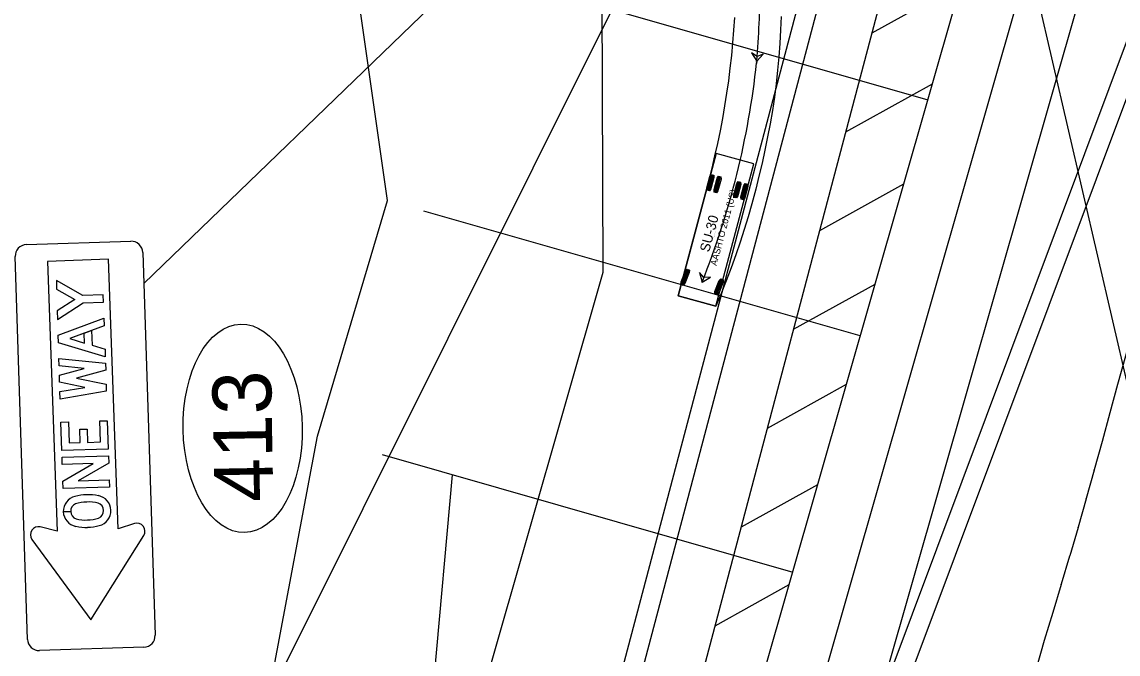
# Model space of a CAD drawing. Extents: x 2096670 to 2098561, y 684033 to 689893.
# Drawn here: x 2097725.3 to 2097948.6, y 689091.3 to 689219.9 of the extents above; entities that cross this region are included whole.
import ezdxf

# ---------------------------------------------------------------- set-up
doc = ezdxf.new("R2010")
doc.units = 0
for name, color, linetype in [('Exist CMT EOP', 7, 'Continuous'), ('Exist Sign E Stop CELL', 7, 'Continuous'), ('Old_Level_63', 7, 'Continuous'), ('Prop Guardrail', 7, 'Continuous'), ('Prop Retaining Wall', 7, 'Continuous'), ('Prop Sign E One Way_Right CELL', 7, 'Continuous'), ('Scratch_Level_2', 7, 'Continuous'), ('Scratch_Level_4', 7, 'Continuous')]:
    doc.layers.add(name, color=color, linetype=linetype)

msp = doc.modelspace()

# ---------------------------------------------------------------- linework, layer by layer
at = {"layer": 'Exist CMT EOP'}
for p, q in [((2097898.92, 689078.74), (2098112.47, 689824.77)), ((2097859.86, 688985.9), (2097968.29, 689364.69)), ((2097822.79, 688994.35), (2097898.87, 689281.72)), ((2097826.66, 688993.33), (2097898.28, 689263.84)), ((2097838.2, 688990.02), (2097909.63, 689259.86)), ((2097875.84, 689085.34), (2097924.62, 689255.73)), ((2097898.47, 689217.7), (2097916.61, 689227.76)), ((2097898.92, 689078.74), (2097951.73, 689219.64)), ((2097902.76, 689077.64), (2097955.58, 689218.54)), ((2097893.15, 689197.59), (2097910.77, 689207.37)), ((2097887.82, 689177.48), (2097904.94, 689186.97)), ((2097882.5, 689157.37), (2097899.1, 689166.58)), ((2097877.18, 689137.26), (2097893.26, 689146.19)), ((2097871.85, 689117.15), (2097887.42, 689125.79)), ((2097866.53, 689097.04), (2097881.58, 689105.4))]:
    msp.add_line(p, q, dxfattribs=at)
at = {"layer": 'Exist Sign E Stop CELL'}
msp.add_line((2097764.4, 689059.94), (2097879.48, 689290.46), dxfattribs=at)
at = {"layer": 'Old_Level_63'}
for p, q in [((2097866.69, 689193.14), (2097858.95, 689164.15)), ((2097874.42, 689191.08), (2097866.69, 689193.14)), ((2097866.68, 689162.09), (2097874.42, 689191.08)), ((2097864.91, 689185.68), (2097865.77, 689188.9)), ((2097865.11, 689185.63), (2097865.97, 689188.85)), ((2097865.32, 689185.57), (2097866.17, 689188.79)), ((2097866.36, 689185.29), (2097867.22, 689188.51)), ((2097866.56, 689185.24), (2097867.42, 689188.46)), ((2097866.76, 689185.18), (2097867.62, 689188.41)), ((2097870.39, 689184.22), (2097871.25, 689187.44)), ((2097870.59, 689184.16), (2097871.45, 689187.38)), ((2097870.79, 689184.11), (2097871.65, 689187.33)), ((2097871.84, 689183.83), (2097872.7, 689187.05)), ((2097872.04, 689183.78), (2097872.9, 689187)), ((2097872.24, 689183.72), (2097873.1, 689186.94)), ((2097859.59, 689166.49), (2097860.83, 689169.58)), ((2097859.78, 689166.41), (2097861.02, 689169.51)), ((2097859.97, 689166.34), (2097861.22, 689169.43)), ((2097866.49, 689164.55), (2097867.72, 689167.64)), ((2097866.68, 689164.47), (2097867.91, 689167.57)), ((2097866.87, 689164.39), (2097868.1, 689167.49)), ((2097858.95, 689164.15), (2097866.68, 689162.09)), ((2097866.68, 689162.09), (2097866.68, 689162.09))]:
    msp.add_line(p, q, dxfattribs=at)
for points in [[(2097879.94, 689221.04), (2097879.81, 689218.3), (2097879.65, 689215.57), (2097879.46, 689212.83), (2097879.23, 689210.1), (2097878.96, 689207.37), (2097878.58, 689204.65), (2097878.17, 689201.94), (2097877.71, 689199.23), (2097877.2, 689196.53), (2097876.66, 689193.85), (2097876.07, 689191.17), (2097875.44, 689188.51), (2097874.77, 689185.88), (2097873.97, 689182.9), (2097873.21, 689180.28), (2097872.42, 689177.68), (2097871.58, 689175.09), (2097870.71, 689172.52), (2097869.76, 689169.88), (2097868.77, 689167.25), (2097867.74, 689164.65), (2097866.68, 689162.09), (2097858.95, 689164.15), (2097865.13, 689187.3), (2097865.87, 689190.16), (2097866.48, 689192.68), (2097867.04, 689195.22), (2097867.57, 689197.75), (2097868.06, 689200.3), (2097868.5, 689202.85), (2097868.91, 689205.41), (2097869.27, 689207.98), (2097869.6, 689210.55), (2097869.88, 689213.12), (2097870.13, 689215.7), (2097870.33, 689218.29), (2097870.49, 689220.87)], [(2097874.98, 689211.93), (2097876.32, 689213.41), (2097875.06, 689212.93), (2097873.9, 689213.62), (2097874.98, 689211.93)], [(2097874.98, 689211.93), (2097874.95, 689211.6)], [(2097863.85, 689166.99), (2097865.57, 689168.01), (2097864.22, 689167.92), (2097863.31, 689168.91), (2097863.85, 689166.99)]]:
    msp.add_lwpolyline(points, dxfattribs=at)
for points in [[(2097874.98, 689211.93), (2097876.32, 689213.41), (2097875.06, 689212.93), (2097873.9, 689213.62)], [(2097865.37, 689185.56), (2097864.86, 689185.69), (2097864.83, 689186.18), (2097865.45, 689188.5), (2097865.72, 689188.91), (2097866.22, 689188.78), (2097866.26, 689188.29), (2097865.64, 689185.97)], [(2097866.81, 689185.17), (2097866.31, 689185.31), (2097866.28, 689185.8), (2097866.9, 689188.12), (2097867.17, 689188.53), (2097867.67, 689188.39), (2097867.71, 689187.9), (2097867.09, 689185.58)], [(2097870.84, 689184.1), (2097870.34, 689184.23), (2097870.31, 689184.72), (2097870.93, 689187.04), (2097871.2, 689187.45), (2097871.7, 689187.32), (2097871.73, 689186.83), (2097871.11, 689184.51)], [(2097872.29, 689183.71), (2097871.79, 689183.84), (2097871.76, 689184.34), (2097872.38, 689186.65), (2097872.65, 689187.06), (2097873.15, 689186.93), (2097873.18, 689186.44), (2097872.56, 689184.12)], [(2097860.02, 689166.32), (2097859.54, 689166.51), (2097859.57, 689167), (2097860.46, 689169.23), (2097860.78, 689169.6), (2097861.27, 689169.41), (2097861.24, 689168.92), (2097860.34, 689166.69)], [(2097863.85, 689166.99), (2097865.57, 689168.01), (2097864.22, 689167.92), (2097863.31, 689168.91)], [(2097866.92, 689164.37), (2097866.44, 689164.56), (2097866.47, 689165.06), (2097867.35, 689167.29), (2097867.67, 689167.66), (2097868.15, 689167.47), (2097868.13, 689166.98), (2097867.24, 689164.75)]]:
    msp.add_lwpolyline(points, close=True, dxfattribs=at)
for centre in [(2097874.95, 689211.6), (2097874.95, 689211.6), (2097874.98, 689211.93), (2097874.98, 689211.93), (2097863.85, 689166.99)]:
    msp.add_circle(centre, 0.0417, dxfattribs=at)
for centre, radius, start, end in [((2097666.07, 689229.38), 209.63, 355.2269, 359.4405), ((2097706.87, 689229.74), 169.06, 338.211, 353.841)]:
    msp.add_arc(centre, radius, start, end, dxfattribs=at)
at = {"layer": 'Prop Guardrail'}
for p, q in [((2097843.25, 689272.72), (2097843.61, 689168.96)), ((2097843.61, 689168.96), (2097820.46, 689088.07))]:
    msp.add_line(p, q, dxfattribs=at)
at = {"layer": 'Prop Retaining Wall'}
msp.add_line((2097808.4, 689076.69), (2097813.04, 689127.77), dxfattribs=at)
at = {"layer": 'Prop Sign E One Way_Right CELL'}
for p, q in [((2097983.65, 689002.74), (2097920.17, 689277.15)), ((2097750.15, 689166.69), (2097861.05, 689273.67)), ((2097726.26, 689174.61), (2097747.51, 689175.3)), ((2097749.95, 689173.02), (2097752.47, 689095.1)), ((2097726.5, 689094.25), (2097723.97, 689172.17)), ((2097735.28, 689120.28), (2097733.76, 689120.23)), ((2097733.76, 689120.23), (2097735.28, 689120.28)), ((2097735.28, 689120.28), (2097733.76, 689120.23)), ((2097733.76, 689120.23), (2097735.28, 689120.28)), ((2097735.28, 689120.28), (2097735.28, 689120.28)), ((2097735.28, 689120.28), (2097735.28, 689120.28)), ((2097750.15, 689115.42), (2097750.15, 689115.42)), ((2097750.19, 689092.66), (2097728.94, 689091.97))]:
    msp.add_line(p, q, dxfattribs=at)
for points in [[(2097748.27, 689117.82), (2097744.91, 689116.74), (2097742.96, 689171.63), (2097730.56, 689171.19), (2097732.52, 689116.29), (2097729.09, 689117.14)], [(2097727.39, 689114.61), (2097739.37, 689098.22), (2097750.15, 689115.42)], [(2097727.39, 689114.61), (2097739.37, 689098.22), (2097750.15, 689115.42)]]:
    msp.add_lwpolyline(points, dxfattribs=at)
for points in [[(2097732.61, 689159.37), (2097737.82, 689162.77), (2097741.95, 689162.91), (2097741.9, 689164.4), (2097737.77, 689164.26), (2097732.35, 689167.32), (2097732.41, 689165.57), (2097736.14, 689163.46), (2097732.55, 689161.12)], [(2097732.61, 689159.37), (2097737.82, 689162.77), (2097741.95, 689162.91), (2097741.9, 689164.4), (2097737.77, 689164.26), (2097732.35, 689167.32), (2097732.41, 689165.57), (2097736.14, 689163.46), (2097732.55, 689161.12)], [(2097732.61, 689159.37), (2097737.82, 689162.77), (2097741.95, 689162.91), (2097741.9, 689164.4), (2097737.77, 689164.26), (2097732.35, 689167.32), (2097732.41, 689165.57), (2097736.14, 689163.46), (2097732.55, 689161.12)], [(2097739.63, 689154.12), (2097742.26, 689153.34), (2097742.31, 689151.77), (2097732.76, 689154.62), (2097732.71, 689156.2), (2097742.05, 689159.67), (2097742.1, 689158.1), (2097739.54, 689157.15)], [(2097742.31, 689151.77), (2097732.76, 689154.62), (2097732.71, 689156.2), (2097742.05, 689159.67), (2097742.1, 689158.1), (2097735.07, 689155.49), (2097738.11, 689154.58), (2097738.04, 689156.59), (2097739.54, 689157.15), (2097739.63, 689154.12), (2097742.26, 689153.34)], [(2097742.31, 689151.77), (2097732.76, 689154.62), (2097732.71, 689156.2), (2097742.05, 689159.67), (2097742.1, 689158.1), (2097735.07, 689155.49), (2097738.11, 689154.58), (2097738.04, 689156.59), (2097739.54, 689157.15), (2097739.63, 689154.12), (2097742.26, 689153.34)], [(2097738.11, 689154.58), (2097738.04, 689156.59), (2097735.07, 689155.49)], [(2097738.17, 689145.55), (2097733.02, 689146.62), (2097732.98, 689148.02), (2097738.05, 689149.42), (2097732.91, 689149.96), (2097732.87, 689151.46), (2097742.35, 689150.46), (2097742.4, 689149.07), (2097736.46, 689147.43), (2097742.49, 689146.18), (2097742.53, 689144.79), (2097733.13, 689143.18), (2097733.09, 689144.68)], [(2097738.17, 689145.55), (2097733.02, 689146.62), (2097732.98, 689148.02), (2097738.05, 689149.42), (2097732.91, 689149.96), (2097732.87, 689151.46), (2097742.35, 689150.46), (2097742.4, 689149.07), (2097736.46, 689147.43), (2097742.49, 689146.18), (2097742.53, 689144.79), (2097733.13, 689143.18), (2097733.09, 689144.68)], [(2097738.17, 689145.55), (2097733.02, 689146.62), (2097732.98, 689148.02), (2097738.05, 689149.42), (2097732.91, 689149.96), (2097732.87, 689151.46), (2097742.35, 689150.46), (2097742.4, 689149.07), (2097736.46, 689147.43), (2097742.49, 689146.18), (2097742.53, 689144.79), (2097733.13, 689143.18), (2097733.09, 689144.68)], [(2097734.8, 689138.51), (2097734.94, 689134.23), (2097737.2, 689134.3), (2097737.12, 689137.01), (2097738.63, 689137.06), (2097738.71, 689134.35), (2097741.36, 689134.44), (2097741.22, 689138.72), (2097742.73, 689138.77), (2097742.92, 689133), (2097733.47, 689132.69), (2097733.29, 689138.46)], [(2097734.8, 689138.51), (2097734.94, 689134.23), (2097737.2, 689134.3), (2097737.12, 689137.01), (2097738.63, 689137.06), (2097738.71, 689134.35), (2097741.36, 689134.44), (2097741.22, 689138.72), (2097742.73, 689138.77), (2097742.92, 689133), (2097733.47, 689132.69), (2097733.29, 689138.46)], [(2097734.8, 689138.51), (2097734.94, 689134.23), (2097737.2, 689134.3), (2097737.12, 689137.01), (2097738.63, 689137.06), (2097738.71, 689134.35), (2097741.36, 689134.44), (2097741.22, 689138.72), (2097742.73, 689138.77), (2097742.92, 689133), (2097733.47, 689132.69), (2097733.29, 689138.46)], [(2097743.17, 689125.25), (2097733.73, 689124.94), (2097733.68, 689126.45), (2097739.85, 689130.03), (2097733.57, 689129.83), (2097733.52, 689131.32), (2097742.96, 689131.62), (2097743.01, 689130.13), (2097736.8, 689126.53), (2097743.12, 689126.74)], [(2097743.17, 689125.25), (2097733.73, 689124.94), (2097733.68, 689126.45), (2097739.85, 689130.03), (2097733.57, 689129.83), (2097733.52, 689131.32), (2097742.96, 689131.62), (2097743.01, 689130.13), (2097736.8, 689126.53), (2097743.12, 689126.74)], [(2097743.17, 689125.25), (2097733.73, 689124.94), (2097733.68, 689126.45), (2097739.85, 689130.03), (2097733.57, 689129.83), (2097733.52, 689131.32), (2097742.96, 689131.62), (2097743.01, 689130.13), (2097736.8, 689126.53), (2097743.12, 689126.74)]]:
    msp.add_lwpolyline(points, close=True, dxfattribs=at)
for centre, radius, start, end in [((2097747.58, 689172.94), 2.36, 1.8562, 91.8571), ((2097726.33, 689172.25), 2.36, 91.8571, 181.8562), ((2097728.7, 689115.57), 1.62, 76.0875, 216.1596), ((2097728.7, 689115.57), 1.62, 76.0875, 216.1596), ((2097748.77, 689116.28), 1.62, 327.9252, 107.9972), ((2097750.11, 689095.02), 2.36, 271.8571, 1.8562), ((2097728.86, 689094.33), 2.36, 181.8562, 271.8571)]:
    msp.add_arc(centre, radius, start, end, dxfattribs=at)
msp.add_ellipse((2097770.29, 689137.21), major_axis=(0.39, -21.22), ratio=0.571429, dxfattribs=at)
for centre, major_axis, start_param, end_param in [((2097738.77, 689114.16), (-9.69, -0.31), 4.707364, 4.955713), ((2097738.77, 689114.16), (-9.69, -0.31), 4.707364, 4.955713), ((2097738.77, 689114.16), (-9.69, -0.31), 4.707364, 4.955713), ((2097738.87, 689114.16), (-9.69, -0.31), 4.469065, 4.717414), ((2097738.87, 689114.16), (-9.69, -0.31), 4.469065, 4.717414), ((2097738.87, 689114.16), (-9.69, -0.31), 4.469065, 4.717414), ((2097740.28, 689120.42), (-3.2, -0.1), 3.1486, 4.483863), ((2097740.28, 689120.42), (-3.2, -0.1), 3.1486, 4.483863), ((2097740.28, 689120.42), (-3.2, -0.1), 3.1486, 4.483863), ((2097736.96, 689120.31), (-3.2, -0.1), 4.940915, 6.276178), ((2097736.96, 689120.31), (-3.2, -0.1), 4.940915, 6.27603), ((2097736.96, 689120.31), (-3.2, -0.1), 4.940915, 6.27603), ((2097736.86, 689120.37), (-1.58, -0.05), 5.062003, 6.314032), ((2097736.86, 689120.37), (-1.58, -0.05), 5.062003, 6.313732), ((2097736.86, 689120.37), (-1.58, -0.05), 5.062003, 6.313732), ((2097738.61, 689115.2), (-7.11, -0.23), 4.688261, 5.016143), ((2097738.61, 689115.2), (-7.11, -0.23), 4.688261, 5.016143), ((2097738.61, 689115.2), (-7.11, -0.23), 4.688261, 5.016143), ((2097738.96, 689115.21), (-7.11, -0.23), 4.408635, 4.736517), ((2097738.96, 689115.21), (-7.11, -0.23), 4.408635, 4.736517), ((2097738.96, 689115.21), (-7.11, -0.23), 4.408635, 4.736517), ((2097740.37, 689120.49), (-1.58, -0.05), 3.110746, 4.362774), ((2097740.37, 689120.49), (-1.58, -0.05), 3.110746, 4.362775), ((2097740.37, 689120.49), (-1.58, -0.05), 3.110746, 4.362775), ((2097736.96, 689120.35), (-3.2, -0.1), 0.007008, 1.34227), ((2097736.96, 689120.35), (-3.2, -0.1), 0.007008, 1.34227), ((2097736.96, 689120.35), (-3.2, -0.1), 0.007008, 1.34227), ((2097736.86, 689120.28), (-1.58, -0.05), 6.252339, 7.504367), ((2097736.86, 689120.28), (-1.58, -0.05), 6.252339, 7.504367), ((2097736.86, 689120.28), (-1.58, -0.05), 6.252339, 7.504367), ((2097740.38, 689120.39), (-1.58, -0.05), 1.920411, 3.172439), ((2097740.38, 689120.39), (-1.58, -0.05), 1.920411, 3.172439), ((2097740.38, 689120.39), (-1.58, -0.05), 1.920411, 3.172439), ((2097740.28, 689120.46), (-3.2, -0.1), 1.799323, 3.134585), ((2097740.28, 689120.46), (-3.2, -0.1), 1.799323, 3.134585), ((2097740.28, 689120.46), (-3.2, -0.1), 1.799323, 3.134585), ((2097738.37, 689126.6), (-9.69, -0.31), 1.327472, 1.575821), ((2097738.37, 689126.6), (-9.69, -0.31), 1.327472, 1.575821), ((2097738.37, 689126.6), (-9.69, -0.31), 1.327472, 1.575821), ((2097738.28, 689125.55), (-7.11, -0.23), 1.267043, 1.594924), ((2097738.28, 689125.55), (-7.11, -0.23), 1.267042, 1.594924), ((2097738.28, 689125.55), (-7.11, -0.23), 1.267042, 1.594924), ((2097738.62, 689125.56), (-7.11, -0.23), 1.546668, 1.87455), ((2097738.62, 689125.56), (-7.11, -0.23), 1.546668, 1.87455), ((2097738.62, 689125.56), (-7.11, -0.23), 1.546668, 1.87455), ((2097738.46, 689126.61), (-9.69, -0.31), 1.565772, 1.814121), ((2097738.46, 689126.61), (-9.69, -0.31), 1.565772, 1.814121), ((2097738.46, 689126.61), (-9.69, -0.31), 1.565772, 1.814121)]:
    msp.add_ellipse(centre, major_axis=major_axis, ratio=0.985, start_param=start_param, end_param=end_param, dxfattribs=at)
at = {"layer": 'Scratch_Level_2'}
for p, q in [((2097795.9, 689236.69), (2097909.83, 689204.08)), ((2097896.07, 689156.01), (2097807.21, 689181.44)), ((2097798.67, 689131.88), (2097882.31, 689107.94))]:
    msp.add_line(p, q, dxfattribs=at)
at = {"layer": 'Scratch_Level_4'}
for p, q in [((2097799.77, 689183.57), (2097792.09, 689237.78)), ((2097785.55, 689135.64), (2097799.77, 689183.57)), ((2097776.14, 689085.72), (2097785.55, 689135.64)), ((2097945.31, 689134.55), (2097943.72, 689128.76)), ((2097943.71, 689128.71), (2097942.09, 689122.93)), ((2097942.08, 689122.87), (2097940.43, 689117.1)), ((2097940.41, 689117.02), (2097938.71, 689111.26)), ((2097938.7, 689111.21), (2097936.98, 689105.46))]:
    msp.add_line(p, q, dxfattribs=at)
for points in [[(2097964.96, 689203.57), (2097963.25, 689197.82), (2097961.55, 689192.08), (2097959.86, 689186.35), (2097958.19, 689180.62), (2097956.54, 689174.88), (2097954.9, 689169.14), (2097953.27, 689163.39), (2097951.66, 689157.64), (2097950.06, 689151.88), (2097948.47, 689146.12), (2097946.89, 689140.34), (2097945.31, 689134.56)], [(2097936.97, 689105.45), (2097935.25, 689099.71), (2097933.54, 689093.99), (2097931.85, 689088.28), (2097930.19, 689082.55), (2097928.53, 689076.8), (2097926.86, 689071.03)]]:
    msp.add_lwpolyline(points, dxfattribs=at)
for centre, start, end in [((2097934.7, 689137.45), 344.6708, 344.7365), ((2097933.11, 689131.67), 344.3942, 344.6708), ((2097931.5, 689125.89), 344.0529, 344.3942), ((2097929.85, 689120.12), 343.6275, 344.0529), ((2097928.16, 689114.36), 343.3475, 343.6275), ((2097926.44, 689108.62), 343.2438, 343.3475)]:
    msp.add_arc(centre, 11, start, end, dxfattribs=at)

# ---------------------------------------------------------------- texts
at = {"layer": 'Old_Level_63'}
for s, height, p in [('AASHTO 2011 (US)', 1.3333, (2097866.79, 689170.22)), ('SU-30', 2, (2097865.28, 689172.96)), ('(c) 2022 Transoft Solutions, Inc. All rights reserved.', 0.08, (2097866.3, 689176.02))]:
    msp.add_text(s, height=height, rotation=75.0561, dxfattribs=at).set_placement(p)
at = {"layer": 'Prop Sign E One Way_Right CELL'}
msp.add_text('413', height=11.98, rotation=91.0659, dxfattribs=at).set_placement((2097776.55, 689122.31))

doc.saveas('drawing.dxf')
